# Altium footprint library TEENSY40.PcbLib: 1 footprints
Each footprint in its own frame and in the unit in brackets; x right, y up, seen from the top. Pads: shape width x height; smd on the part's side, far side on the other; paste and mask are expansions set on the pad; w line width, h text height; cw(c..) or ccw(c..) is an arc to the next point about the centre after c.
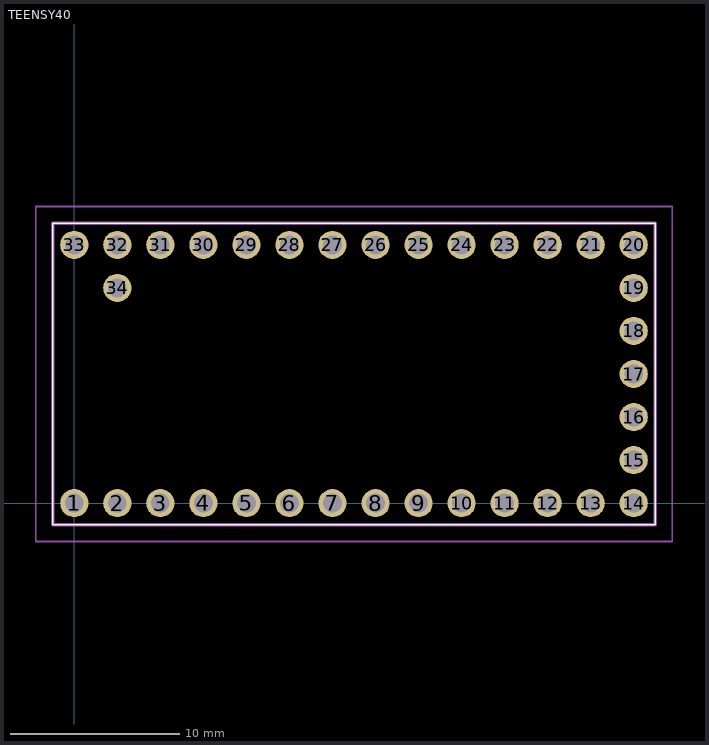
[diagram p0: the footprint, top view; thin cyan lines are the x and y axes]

## TEENSY40 [mm]
pads (34):
  round 1.665 hole 1.11: 1(0,0) 2(2.54,0) 3(5.08,0) 4(7.62,0) 5(10.16,0) 6(12.7,0) 7(15.24,0) 8(17.78,0) 9(20.32,0) 10(22.86,0) 11(25.4,0) 12(27.94,0) 13(30.48,0) 14(33.02,0) 15(33.02,2.54) 16(33.02,5.08) 17(33.02,7.62) 18(33.02,10.16) 19(33.02,12.7) 20(33.02,15.24) 21(30.48,15.24) 22(27.94,15.24) 23(25.4,15.24) 24(22.86,15.24) 25(20.32,15.24) 26(17.78,15.24) 27(15.24,15.24) 28(12.7,15.24) 29(10.16,15.24) 30(7.62,15.24) 31(5.08,15.24) 32(2.54,15.24) 33(0,15.24) 34(2.54,12.7)
Top Overlay:
  lines w0.1: -1.27,-1.27 34.29,-1.27 34.29,16.51 -1.27,16.51 -1.27,-1.27
Mechanical 15:
  lines w0.2: -1.27,-1.27 34.29,-1.27 34.29,16.51 -1.27,16.51 -1.27,-1.27
Mechanical 20:
  lines w0.1: -2.27,-2.27 35.29,-2.27 35.29,17.51 -2.27,17.51 -2.27,-2.27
